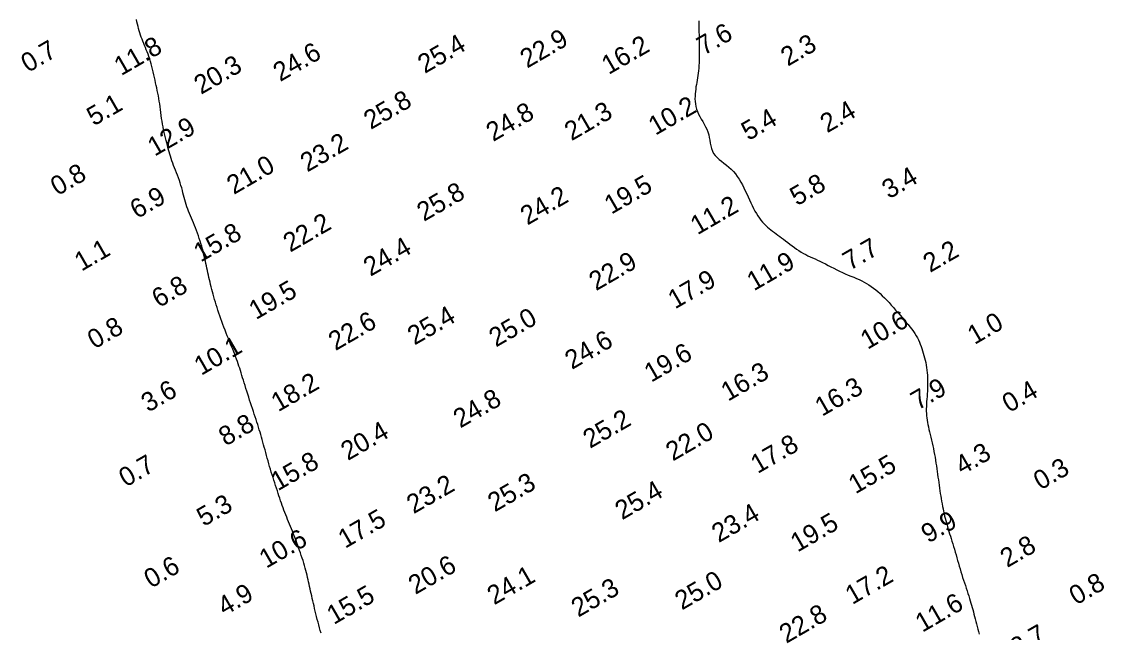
# Model space of a CAD drawing. Extents: x 3024098 to 3056816, y 418252 to 509144.
# Drawn here: x 3028066.7 to 3028353, y 427165.1 to 427326.7 of the extents above; entities that cross this region are included whole.
import ezdxf

# ---------------------------------------------------------------- set-up
doc = ezdxf.new("R2010")
doc.units = 0
doc.layers.add('V-CHAN-CONT-EL10', color=7, linetype='Continuous')
doc.layers.add('V-TOPO-SOUN-0911', color=7, linetype='Continuous')

msp = doc.modelspace()

# ---------------------------------------------------------------- linework, layer by layer
at = {"layer": 'V-CHAN-CONT-EL10'}
for points in [[(3028145.87, 427164.9), (3028145.65, 427165.63), (3028145.44, 427166.37), (3028145.24, 427167.1), (3028145.05, 427167.84), (3028144.86, 427168.57), (3028144.68, 427169.3), (3028144.5, 427170.02), (3028144.33, 427170.73), (3028144.16, 427171.43), (3028144, 427172.12), (3028143.84, 427172.8), (3028143.68, 427173.47), (3028143.53, 427174.13), (3028143.38, 427174.77), (3028143.24, 427175.41), (3028143.1, 427176.04), (3028142.96, 427176.66), (3028142.83, 427177.27), (3028142.7, 427177.87), (3028142.57, 427178.47), (3028142.44, 427179.07), (3028142.3, 427179.67), (3028142.16, 427180.27), (3028142.02, 427180.89), (3028141.86, 427181.51), (3028141.68, 427182.14), (3028141.5, 427182.79), (3028141.29, 427183.45), (3028141.08, 427184.13), (3028140.86, 427184.8), (3028140.63, 427185.48), (3028140.4, 427186.16), (3028140.16, 427186.84), (3028139.93, 427187.5), (3028139.69, 427188.16), (3028139.46, 427188.81), (3028139.23, 427189.45), (3028138.99, 427190.08), (3028138.76, 427190.7), (3028138.52, 427191.33), (3028138.28, 427191.94), (3028138.03, 427192.56), (3028137.78, 427193.17), (3028137.53, 427193.79), (3028137.27, 427194.4), (3028137.01, 427195.02), (3028136.76, 427195.63), (3028136.51, 427196.25), (3028136.26, 427196.86), (3028136.02, 427197.48), (3028135.79, 427198.1), (3028135.57, 427198.72), (3028135.35, 427199.34), (3028135.14, 427199.97), (3028134.93, 427200.61), (3028134.71, 427201.26), (3028134.5, 427201.91), (3028134.29, 427202.58), (3028134.06, 427203.26), (3028133.84, 427203.95), (3028133.61, 427204.66), (3028133.38, 427205.37), (3028133.15, 427206.09), (3028132.92, 427206.81), (3028132.69, 427207.54), (3028132.47, 427208.28), (3028132.25, 427209.02), (3028132.04, 427209.76), (3028131.83, 427210.5), (3028131.62, 427211.23), (3028131.42, 427211.96), (3028131.23, 427212.69), (3028131.03, 427213.4), (3028130.84, 427214.1), (3028130.66, 427214.79), (3028130.47, 427215.46), (3028130.29, 427216.13), (3028130.1, 427216.79), (3028129.91, 427217.45), (3028129.72, 427218.1), (3028129.52, 427218.76), (3028129.32, 427219.42), (3028129.11, 427220.09), (3028128.89, 427220.77), (3028128.66, 427221.46), (3028128.43, 427222.15), (3028128.2, 427222.86), (3028127.96, 427223.58), (3028127.71, 427224.32), (3028127.47, 427225.07), (3028127.22, 427225.83), (3028126.97, 427226.6), (3028126.71, 427227.38), (3028126.47, 427228.15), (3028126.22, 427228.92), (3028125.98, 427229.68), (3028125.75, 427230.42), (3028125.53, 427231.13), (3028125.32, 427231.82), (3028125.12, 427232.49), (3028124.93, 427233.13), (3028124.73, 427233.76), (3028124.54, 427234.38), (3028124.35, 427234.99), (3028124.15, 427235.6), (3028123.94, 427236.21), (3028123.72, 427236.83), (3028123.49, 427237.45), (3028123.25, 427238.08), (3028123.01, 427238.72), (3028122.75, 427239.37), (3028122.48, 427240.04), (3028122.21, 427240.72), (3028121.93, 427241.41), (3028121.64, 427242.12), (3028121.34, 427242.84), (3028121.04, 427243.58), (3028120.74, 427244.32), (3028120.45, 427245.07), (3028120.15, 427245.83), (3028119.87, 427246.59), (3028119.59, 427247.34), (3028119.32, 427248.1), (3028119.06, 427248.85), (3028118.81, 427249.6), (3028118.58, 427250.34), (3028118.35, 427251.07), (3028118.13, 427251.8), (3028117.92, 427252.51), (3028117.71, 427253.21), (3028117.52, 427253.89), (3028117.33, 427254.57), (3028117.15, 427255.23), (3028116.98, 427255.88), (3028116.81, 427256.52), (3028116.65, 427257.15), (3028116.5, 427257.78), (3028116.35, 427258.4), (3028116.2, 427259.01), (3028116.06, 427259.63), (3028115.93, 427260.24), (3028115.79, 427260.85), (3028115.66, 427261.46), (3028115.52, 427262.08), (3028115.39, 427262.71), (3028115.25, 427263.34), (3028115.11, 427263.98), (3028114.96, 427264.62), (3028114.8, 427265.28), (3028114.64, 427265.94), (3028114.47, 427266.61), (3028114.28, 427267.29), (3028114.08, 427267.97), (3028113.87, 427268.66), (3028113.64, 427269.35), (3028113.4, 427270.04), (3028113.15, 427270.73), (3028112.89, 427271.42), (3028112.62, 427272.11), (3028112.35, 427272.78), (3028112.08, 427273.44), (3028111.81, 427274.09), (3028111.55, 427274.72), (3028111.3, 427275.33), (3028111.05, 427275.94), (3028110.81, 427276.54), (3028110.58, 427277.13), (3028110.37, 427277.72), (3028110.16, 427278.31), (3028109.98, 427278.91), (3028109.8, 427279.52), (3028109.64, 427280.14), (3028109.48, 427280.76), (3028109.33, 427281.4), (3028109.17, 427282.04), (3028109, 427282.69), (3028108.81, 427283.35), (3028108.61, 427284.01), (3028108.39, 427284.68), (3028108.14, 427285.36), (3028107.89, 427286.04), (3028107.62, 427286.71), (3028107.36, 427287.37), (3028107.1, 427288.03), (3028106.85, 427288.67), (3028106.61, 427289.29), (3028106.4, 427289.9), (3028106.2, 427290.49), (3028106.02, 427291.07), (3028105.85, 427291.64), (3028105.68, 427292.22), (3028105.52, 427292.8), (3028105.36, 427293.39), (3028105.2, 427294), (3028105.04, 427294.64), (3028104.87, 427295.29), (3028104.7, 427295.97), (3028104.53, 427296.66), (3028104.37, 427297.37), (3028104.21, 427298.09), (3028104.06, 427298.83), (3028103.93, 427299.58), (3028103.8, 427300.34), (3028103.68, 427301.11), (3028103.58, 427301.88), (3028103.47, 427302.65), (3028103.37, 427303.42), (3028103.27, 427304.17), (3028103.17, 427304.92), (3028103.06, 427305.66), (3028102.94, 427306.38), (3028102.82, 427307.08), (3028102.68, 427307.78), (3028102.55, 427308.46), (3028102.4, 427309.15), (3028102.26, 427309.84), (3028102.1, 427310.53), (3028101.95, 427311.23), (3028101.79, 427311.94), (3028101.63, 427312.66), (3028101.47, 427313.38), (3028101.3, 427314.09), (3028101.12, 427314.8), (3028100.93, 427315.5), (3028100.74, 427316.19), (3028100.54, 427316.85), (3028100.32, 427317.48), (3028100.1, 427318.1), (3028099.87, 427318.69), (3028099.64, 427319.27), (3028099.4, 427319.83), (3028099.17, 427320.39), (3028098.94, 427320.94), (3028098.72, 427321.49), (3028098.51, 427322.04), (3028098.31, 427322.59), (3028098.12, 427323.15), (3028097.93, 427323.71), (3028097.76, 427324.28), (3028097.59, 427324.85), (3028097.44, 427325.44), (3028097.29, 427326.04), (3028097.15, 427326.65), (3028097.02, 427327.27)], [(3028245.74, 427326.93), (3028245.75, 427326.25), (3028245.76, 427325.54), (3028245.77, 427324.78), (3028245.79, 427323.98), (3028245.81, 427323.14), (3028245.83, 427322.29), (3028245.85, 427321.43), (3028245.87, 427320.56), (3028245.88, 427319.71), (3028245.89, 427318.87), (3028245.88, 427318.05), (3028245.87, 427317.26), (3028245.85, 427316.5), (3028245.82, 427315.76), (3028245.78, 427315.05), (3028245.73, 427314.36), (3028245.66, 427313.69), (3028245.59, 427313.04), (3028245.5, 427312.42), (3028245.41, 427311.82), (3028245.31, 427311.22), (3028245.21, 427310.63), (3028245.11, 427310.04), (3028245.01, 427309.45), (3028244.93, 427308.85), (3028244.85, 427308.23), (3028244.8, 427307.6), (3028244.76, 427306.94), (3028244.75, 427306.28), (3028244.78, 427305.6), (3028244.85, 427304.92), (3028244.97, 427304.24), (3028245.14, 427303.56), (3028245.38, 427302.89), (3028245.67, 427302.22), (3028246.02, 427301.56), (3028246.4, 427300.9), (3028246.79, 427300.24), (3028247.18, 427299.58), (3028247.55, 427298.9), (3028247.89, 427298.21), (3028248.17, 427297.51), (3028248.38, 427296.78), (3028248.54, 427296.04), (3028248.68, 427295.3), (3028248.8, 427294.56), (3028248.94, 427293.84), (3028249.12, 427293.14), (3028249.36, 427292.47), (3028249.68, 427291.85), (3028250.09, 427291.28), (3028250.58, 427290.75), (3028251.15, 427290.24), (3028251.76, 427289.75), (3028252.4, 427289.26), (3028253.05, 427288.76), (3028253.69, 427288.23), (3028254.31, 427287.67), (3028254.89, 427287.07), (3028255.43, 427286.42), (3028255.93, 427285.73), (3028256.4, 427285.02), (3028256.85, 427284.27), (3028257.27, 427283.51), (3028257.67, 427282.73), (3028258.05, 427281.93), (3028258.43, 427281.14), (3028258.79, 427280.34), (3028259.15, 427279.56), (3028259.51, 427278.78), (3028259.87, 427278.03), (3028260.23, 427277.29), (3028260.6, 427276.6), (3028260.99, 427275.93), (3028261.38, 427275.31), (3028261.79, 427274.73), (3028262.2, 427274.19), (3028262.63, 427273.68), (3028263.06, 427273.21), (3028263.5, 427272.77), (3028263.94, 427272.35), (3028264.39, 427271.96), (3028264.84, 427271.59), (3028265.29, 427271.24), (3028265.74, 427270.9), (3028266.21, 427270.56), (3028266.68, 427270.23), (3028267.17, 427269.88), (3028267.67, 427269.51), (3028268.19, 427269.13), (3028268.73, 427268.72), (3028269.29, 427268.29), (3028269.86, 427267.85), (3028270.44, 427267.41), (3028271.04, 427266.96), (3028271.63, 427266.53), (3028272.23, 427266.12), (3028272.83, 427265.74), (3028273.43, 427265.4), (3028274.03, 427265.07), (3028274.63, 427264.77), (3028275.24, 427264.48), (3028275.86, 427264.2), (3028276.49, 427263.91), (3028277.14, 427263.61), (3028277.81, 427263.3), (3028278.51, 427262.95), (3028279.23, 427262.59), (3028279.96, 427262.21), (3028280.71, 427261.83), (3028281.46, 427261.44), (3028282.22, 427261.05), (3028282.99, 427260.68), (3028283.75, 427260.33), (3028284.51, 427259.99), (3028285.26, 427259.67), (3028286, 427259.36), (3028286.73, 427259.06), (3028287.45, 427258.76), (3028288.15, 427258.46), (3028288.84, 427258.14), (3028289.5, 427257.8), (3028290.14, 427257.45), (3028290.76, 427257.07), (3028291.37, 427256.66), (3028291.97, 427256.22), (3028292.55, 427255.76), (3028293.13, 427255.27), (3028293.71, 427254.75), (3028294.29, 427254.2), (3028294.88, 427253.61), (3028295.47, 427252.99), (3028296.06, 427252.36), (3028296.65, 427251.71), (3028297.24, 427251.04), (3028297.82, 427250.38), (3028298.4, 427249.71), (3028298.97, 427249.05), (3028299.53, 427248.41), (3028300.08, 427247.78), (3028300.61, 427247.15), (3028301.12, 427246.54), (3028301.61, 427245.94), (3028302.07, 427245.35), (3028302.5, 427244.76), (3028302.89, 427244.19), (3028303.24, 427243.62), (3028303.56, 427243.05), (3028303.85, 427242.49), (3028304.11, 427241.93), (3028304.34, 427241.36), (3028304.56, 427240.79), (3028304.76, 427240.21), (3028304.95, 427239.63), (3028305.13, 427239.03), (3028305.31, 427238.41), (3028305.47, 427237.79), (3028305.62, 427237.16), (3028305.77, 427236.51), (3028305.89, 427235.86), (3028306, 427235.19), (3028306.09, 427234.52), (3028306.16, 427233.83), (3028306.21, 427233.14), (3028306.25, 427232.45), (3028306.27, 427231.75), (3028306.27, 427231.05), (3028306.26, 427230.34), (3028306.24, 427229.64), (3028306.21, 427228.94), (3028306.17, 427228.25), (3028306.12, 427227.56), (3028306.07, 427226.87), (3028306.02, 427226.2), (3028305.98, 427225.54), (3028305.95, 427224.89), (3028305.93, 427224.26), (3028305.93, 427223.64), (3028305.96, 427223.04), (3028306, 427222.45), (3028306.06, 427221.86), (3028306.14, 427221.28), (3028306.24, 427220.69), (3028306.36, 427220.09), (3028306.49, 427219.47), (3028306.63, 427218.83), (3028306.78, 427218.16), (3028306.94, 427217.47), (3028307.11, 427216.75), (3028307.28, 427216.01), (3028307.46, 427215.26), (3028307.62, 427214.5), (3028307.79, 427213.74), (3028307.95, 427212.97), (3028308.09, 427212.21), (3028308.23, 427211.45), (3028308.36, 427210.69), (3028308.48, 427209.93), (3028308.6, 427209.18), (3028308.71, 427208.43), (3028308.81, 427207.69), (3028308.91, 427206.95), (3028309.01, 427206.22), (3028309.11, 427205.49), (3028309.21, 427204.76), (3028309.31, 427204.04), (3028309.41, 427203.33), (3028309.51, 427202.62), (3028309.62, 427201.91), (3028309.73, 427201.21), (3028309.85, 427200.51), (3028309.97, 427199.82), (3028310.09, 427199.14), (3028310.22, 427198.47), (3028310.36, 427197.81), (3028310.49, 427197.16), (3028310.64, 427196.53), (3028310.78, 427195.92), (3028310.93, 427195.33), (3028311.08, 427194.74), (3028311.23, 427194.17), (3028311.4, 427193.6), (3028311.56, 427193.03), (3028311.73, 427192.45), (3028311.91, 427191.85), (3028312.1, 427191.23), (3028312.29, 427190.6), (3028312.5, 427189.93), (3028312.7, 427189.25), (3028312.91, 427188.55), (3028313.13, 427187.84), (3028313.34, 427187.11), (3028313.56, 427186.38), (3028313.78, 427185.64), (3028313.99, 427184.9), (3028314.21, 427184.15), (3028314.42, 427183.41), (3028314.64, 427182.66), (3028314.85, 427181.92), (3028315.08, 427181.17), (3028315.3, 427180.43), (3028315.53, 427179.69), (3028315.77, 427178.96), (3028316.01, 427178.23), (3028316.25, 427177.51), (3028316.48, 427176.8), (3028316.72, 427176.11), (3028316.95, 427175.43), (3028317.16, 427174.77), (3028317.37, 427174.13), (3028317.56, 427173.51), (3028317.74, 427172.91), (3028317.91, 427172.31), (3028318.07, 427171.73), (3028318.23, 427171.15), (3028318.38, 427170.56), (3028318.53, 427169.96), (3028318.69, 427169.34), (3028318.85, 427168.7), (3028319.01, 427168.05), (3028319.17, 427167.38), (3028319.34, 427166.7), (3028319.52, 427166.02), (3028319.69, 427165.34), (3028319.87, 427164.65)]]:
    msp.add_lwpolyline(points, dxfattribs=at)

# ---------------------------------------------------------------- texts
at = {"layer": 'V-TOPO-SOUN-0911'}
for s, p in [('22.9 ', (3028200.36, 427314.26)), ('7.6', (3028247.08, 427317.65)), ('0.7', (3028068.34, 427313.09)), ('11.8 ', (3028092.98, 427312.26)), ('25.4 ', (3028173.29, 427312.85)), ('16.2 ', (3028221.91, 427312.56)), ('2.3', (3028269.29, 427314.76)), ('24.6 ', (3028135.04, 427310.69)), ('20.3 ', (3028114.11, 427307.31)), ('25.8 ', (3028158.99, 427298.02)), ('5.1', (3028085.74, 427298.96)), ('24.8 ', (3028191.37, 427294.84)), ('21.3 ', (3028212.1, 427295.04)), ('10.2 ', (3028234.28, 427296.48)), ('2.4', (3028279.72, 427297.14)), ('5.4', (3028258.86, 427295.08)), ('12.9 ', (3028101.84, 427290.94)), ('23.2 ', (3028142.22, 427286.77)), ('21.0 ', (3028122.78, 427280.83)), ('0.8', (3028076.15, 427280.51)), ('3.4', (3028296.06, 427279.66)), ('19.5 ', (3028222.63, 427275.61)), ('5.8', (3028271.72, 427277.82)), ('6.9', (3028097.18, 427274.41)), ('25.8 ', (3028173.06, 427273.71)), ('24.2 ', (3028200.42, 427272.73)), ('11.2 ', (3028245.4, 427270.17)), ('22.2 ', (3028137.7, 427265.57)), ('15.8 ', (3028114.01, 427262.95)), ('1.1', (3028082.49, 427260.54)), ('24.4 ', (3028158.92, 427259.18)), ('7.7', (3028285.69, 427260.76)), ('2.2', (3028306.92, 427260.2)), ('22.9 ', (3028218.57, 427255.37)), ('11.9 ', (3028260.33, 427255.34)), ('6.8', (3028102.95, 427250.88)), ('17.9 ', (3028239.47, 427250.55)), ('19.5 ', (3028128.63, 427247.73)), ('22.6 ', (3028149.67, 427239.53)), ('25.4 ', (3028170.57, 427241)), ('25.0 ', (3028192.11, 427240.47)), ('10.6 ', (3028290.38, 427239.86)), ('0.8', (3028085.92, 427239.96)), ('1.0', (3028318.68, 427241.14)), ('24.6 ', (3028212.2, 427234.54)), ('10.1 ', (3028114.15, 427232.98)), ('19.6 ', (3028233.17, 427231.16)), ('16.3 ', (3028253.48, 427226.14)), ('18.2 ', (3028134.51, 427223.35)), ('3.6', (3028100.13, 427223.23)), ('16.3 ', (3028278.34, 427222.14)), ('7.9', (3028303.67, 427223.78)), ('0.4', (3028327.85, 427223.13)), ('24.8 ', (3028182.68, 427219.05)), ('8.8', (3028120.63, 427214.3)), ('25.2 ', (3028216.99, 427213.67)), ('20.4 ', (3028152.95, 427210.46)), ('22.0 ', (3028238.89, 427210.32)), ('17.8 ', (3028261.32, 427207.01)), ('4.3', (3028315.42, 427206.66)), ('0.7', (3028094.22, 427203.44)), ('15.8 ', (3028134.45, 427202.45)), ('15.5 ', (3028287.19, 427201.63)), ('0.3', (3028336.12, 427202.65)), ('25.3 ', (3028191.8, 427196.87)), ('23.2 ', (3028170.34, 427196.38)), ('25.4 ', (3028225.46, 427194.77)), ('5.3', (3028114.83, 427193.01)), ('23.4 ', (3028251.02, 427188.74)), ('17.5 ', (3028152.22, 427187.23)), ('19.5 ', (3028271.87, 427186.24)), ('9.9', (3028306.43, 427188.61)), ('10.6 ', (3028131.36, 427181.95)), ('2.8', (3028327.33, 427182.15)), ('0.6', (3028100.88, 427176.68)), ('20.6 ', (3028170.8, 427175.03)), ('24.1 ', (3028191.65, 427172.28)), ('25.0 ', (3028241.29, 427170.92)), ('17.2 ', (3028286.35, 427172.37)), ('25.3 ', (3028213.88, 427169.02)), ('0.8', (3028345.57, 427172.24)), ('4.9', (3028120.34, 427169.42)), ('15.5 ', (3028149.23, 427167.08)), ('11.6 ', (3028304.88, 427165.02)), ('22.8 ', (3028268.9, 427162.1)), ('3.7', (3028330.02, 427158.56))]:
    msp.add_text(s, height=5, rotation=30, dxfattribs=at).set_placement(p)

doc.saveas('drawing.dxf')
